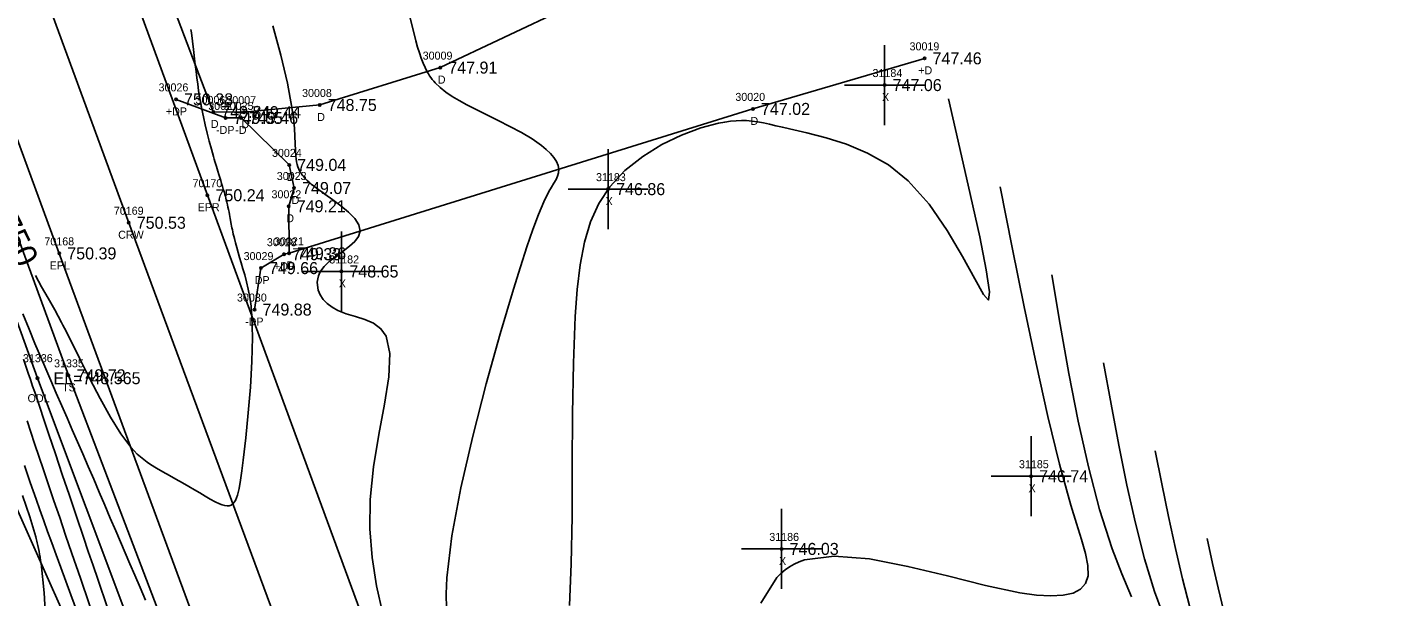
# Model space of a CAD drawing. Extents: x 1376587 to 1378239, y 1000335 to 1003031.
# Drawn here: x 1376699.8 to 1376870.4, y 1002859.9 to 1002931 of the extents above; entities that cross this region are included whole.
import ezdxf

# ---------------------------------------------------------------- set-up
doc = ezdxf.new("R2010")
doc.units = 0
for name, color, linetype in [('RD_DTM_BkLn1', 7, 'Continuous'), ('RD_DTM_BkLn2', 7, 'Continuous'), ('RD_DTM_BkLn_txCode', 7, 'Continuous'), ('RD_DTM_Major1', 7, 'Continuous'), ('RD_DTM_Major1_Lbl', 7, 'Continuous'), ('RD_DTM_Minor1', 7, 'Continuous'), ('RD_EX_Driveway', 7, 'Continuous'), ('RD_EX_Driveway_txCode', 7, 'Continuous'), ('RD_EX_H2O', 7, 'Continuous'), ('RD_EX_H2O_txCode', 7, 'Continuous'), ('RD_EX_Misc', 7, 'Continuous'), ('RD_EX_Misc_txCode', 7, 'Continuous'), ('RD_EX_Road', 7, 'Continuous'), ('RD_EX_Road_txCode', 7, 'Continuous'), ('RD_EX_TX_Driveway_ELEV', 7, 'Continuous'), ('RD_EX_TX_H2O_ELEV', 7, 'Continuous'), ('RD_EX_TX_Misc_ELEV', 7, 'Continuous'), ('RD_EX_TX_Road_ELEV', 7, 'Continuous'), ('RD_HC_Survey_ELEV', 7, 'Continuous'), ('RD_HC_Survey_txCode', 7, 'Continuous'), ('RD_SMD_Locator', 7, 'Continuous')]:
    doc.layers.add(name, color=color, linetype=linetype)

msp = doc.modelspace()

# ---------------------------------------------------------------- linework, layer by layer
at = {"layer": 'RD_DTM_BkLn1'}
msp.add_lwpolyline([(1376777.12, 1002732.3), (1376776.77, 1002733.82), (1376754.91, 1002791.11), (1376734.25, 1002847.87), (1376712.48, 1002906.61), (1376690.98, 1002965.02), (1376668.66, 1003026.02)], dxfattribs=at)
at = {"layer": 'RD_DTM_BkLn2'}
for points in [[(1376885.61, 1002428.98), (1376889.78, 1002434.68), (1376874.69, 1002468.75), (1376852.19, 1002514.33), (1376831.8, 1002561.56), (1376809.96, 1002613.35), (1376792.97, 1002652.8), (1376775.33, 1002700.18), (1376756.39, 1002747.21), (1376739.8, 1002794.07), (1376723.1, 1002839.91), (1376704.95, 1002887.54), (1376687.77, 1002934.36), (1376670.41, 1002980.85)], [(1376885.61, 1002428.97), (1376881.3, 1002430.18), (1376863.13, 1002464.59), (1376838.71, 1002510.16), (1376821.82, 1002559.18), (1376802.89, 1002607.61), (1376786.81, 1002643.28), (1376765.51, 1002696.1), (1376748.39, 1002745.62), (1376732.07, 1002790.52), (1376713.54, 1002837.08), (1376692.71, 1002883.81), (1376675.42, 1002930.22), (1376657.29, 1002975.68)]]:
    msp.add_lwpolyline(points, dxfattribs=at)
at = {"layer": 'RD_DTM_Major1'}
for points in [[(1376720.26, 1002930.77), (1376720.32, 1002930.36), (1376720.45, 1002929.3), (1376720.58, 1002928.27), (1376720.8, 1002926.36), (1376720.9, 1002925.52), (1376721, 1002924.71), (1376721.1, 1002923.92), (1376721.21, 1002923.14), (1376721.33, 1002922.36), (1376721.47, 1002921.57), (1376721.49, 1002921.45), (1376721.52, 1002921.32), (1376721.54, 1002921.2), (1376721.56, 1002921.07), (1376721.61, 1002920.82), (1376721.81, 1002919.85), (1376722.04, 1002918.84), (1376722.29, 1002917.82), (1376722.55, 1002916.8), (1376722.81, 1002915.82), (1376723.06, 1002914.9), (1376723.16, 1002914.57), (1376723.25, 1002914.25), (1376723.44, 1002913.64), (1376723.52, 1002913.35), (1376723.61, 1002913.07), (1376723.74, 1002912.65), (1376723.98, 1002911.88), (1376724.09, 1002911.51), (1376724.2, 1002911.16), (1376724.3, 1002910.82), (1376724.44, 1002910.37), (1376724.5, 1002910.14), (1376724.56, 1002909.92), (1376724.61, 1002909.7), (1376724.67, 1002909.48), (1376724.74, 1002909.17), (1376724.82, 1002908.86), (1376724.88, 1002908.55), (1376724.95, 1002908.25), (1376725.01, 1002907.94), (1376725.07, 1002907.63), (1376725.11, 1002907.39), (1376725.16, 1002907.16), (1376725.29, 1002906.45), (1376725.34, 1002906.2), (1376725.38, 1002905.96), (1376725.44, 1002905.71), (1376725.49, 1002905.46), (1376725.55, 1002905.2), (1376725.61, 1002904.94), (1376725.68, 1002904.66), (1376725.82, 1002904.11), (1376725.98, 1002903.52), (1376726.15, 1002902.91), (1376726.34, 1002902.26), (1376726.54, 1002901.58), (1376726.75, 1002900.87), (1376726.97, 1002900.08), (1376727.2, 1002899.23), (1376727.41, 1002898.32), (1376727.6, 1002897.31), (1376727.76, 1002896.19), (1376727.87, 1002894.94), (1376727.95, 1002892.27), (1376727.87, 1002889.26), (1376727.68, 1002886.06), (1376727.41, 1002882.83), (1376727.1, 1002879.74), (1376726.79, 1002876.92), (1376726.63, 1002875.6), (1376726.46, 1002874.42), (1376726.28, 1002873.4), (1376726.07, 1002872.55), (1376725.81, 1002871.91), (1376725.5, 1002871.47), (1376725.28, 1002871.32), (1376725.04, 1002871.24), (1376724.77, 1002871.22), (1376724.48, 1002871.26), (1376724.17, 1002871.35), (1376723.84, 1002871.48), (1376723.27, 1002871.74), (1376722.67, 1002872.06), (1376722.04, 1002872.43), (1376721.37, 1002872.83), (1376720.69, 1002873.24), (1376719.99, 1002873.66), (1376719.18, 1002874.12), (1376718.37, 1002874.57), (1376717.56, 1002875.01), (1376716.76, 1002875.47), (1376715.97, 1002875.93), (1376715.21, 1002876.41), (1376714.79, 1002876.7), (1376714.37, 1002877), (1376713.96, 1002877.33), (1376713.55, 1002877.69), (1376713.14, 1002878.1), (1376712.73, 1002878.55), (1376711.48, 1002880.23), (1376710.2, 1002882.29), (1376708.91, 1002884.63), (1376707.63, 1002887.11), (1376706.39, 1002889.6), (1376705.2, 1002891.97), (1376705.01, 1002892.35), (1376704.82, 1002892.72), (1376704.45, 1002893.45), (1376704.26, 1002893.8), (1376704.08, 1002894.15), (1376703.23, 1002895.71), (1376702.41, 1002897.2), (1376701.6, 1002898.62), (1376700.83, 1002900)], [(1376827.83, 1002900.11), (1376828.88, 1002893.89), (1376829.97, 1002887.75), (1376831.13, 1002881.79), (1376832.39, 1002876.09), (1376833.79, 1002870.75), (1376835.36, 1002865.84), (1376836.56, 1002862.72), (1376837.77, 1002859.86)], [(1376699.77, 1002881.83), (1376700.23, 1002880.44), (1376700.71, 1002879.02), (1376701.82, 1002875.74), (1376702.47, 1002873.84), (1376703.14, 1002871.84), (1376703.85, 1002869.76), (1376704.59, 1002867.57), (1376705.38, 1002865.28), (1376706.44, 1002862.18), (1376707.55, 1002858.98), (1376708.67, 1002855.76), (1376709.77, 1002852.58), (1376710.82, 1002849.54), (1376711.8, 1002846.71), (1376712.38, 1002845.01), (1376712.93, 1002843.41), (1376713.44, 1002841.92), (1376713.93, 1002840.5), (1376714.39, 1002839.15), (1376714.53, 1002838.74)]]:
    msp.add_lwpolyline(points, dxfattribs=at)
at = {"layer": 'RD_DTM_Minor1'}
for points in [[(1376730.49, 1002931.23), (1376731.47, 1002927.54), (1376732.3, 1002924.06), (1376732.88, 1002921), (1376733.06, 1002919.64), (1376733.18, 1002918.45), (1376733.24, 1002917.4), (1376733.31, 1002915.66), (1376733.36, 1002914.95), (1376733.4, 1002914.58), (1376733.46, 1002914.24), (1376733.53, 1002913.91), (1376733.62, 1002913.6), (1376733.74, 1002913.31), (1376733.88, 1002913.03), (1376734.01, 1002912.8), (1376734.17, 1002912.57), (1376734.35, 1002912.35), (1376734.54, 1002912.12), (1376734.77, 1002911.9), (1376735.01, 1002911.67), (1376735.28, 1002911.44), (1376735.58, 1002911.21), (1376735.89, 1002910.96), (1376736.23, 1002910.71), (1376736.59, 1002910.46), (1376736.97, 1002910.19), (1376737.97, 1002909.48), (1376738.99, 1002908.72), (1376739.94, 1002907.93), (1376740.72, 1002907.12), (1376741.23, 1002906.33), (1376741.4, 1002905.56), (1376741.2, 1002904.9), (1376740.72, 1002904.27), (1376740.05, 1002903.67), (1376739.27, 1002903.07), (1376738.45, 1002902.49), (1376737.68, 1002901.9), (1376737.54, 1002901.77), (1376737.4, 1002901.65), (1376737.26, 1002901.52), (1376737.13, 1002901.4), (1376737.01, 1002901.27), (1376736.9, 1002901.14), (1376736.6, 1002900.76), (1376736.37, 1002900.38), (1376736.2, 1002899.99), (1376736.09, 1002899.59), (1376736.04, 1002899.19), (1376736.05, 1002898.79), (1376736.17, 1002898.19), (1376736.42, 1002897.59), (1376736.79, 1002897.03), (1376737.28, 1002896.51), (1376737.89, 1002896.05), (1376738.59, 1002895.65), (1376739.66, 1002895.24), (1376740.82, 1002894.89), (1376741.98, 1002894.52), (1376743.06, 1002894.04), (1376743.99, 1002893.37), (1376744.66, 1002892.42), (1376745.12, 1002890.26), (1376744.98, 1002887.37), (1376744.45, 1002883.94), (1376743.74, 1002880.13), (1376743.07, 1002876.1), (1376742.64, 1002872.02), (1376742.61, 1002868.36), (1376742.9, 1002864.77), (1376743.46, 1002861.23), (1376744.24, 1002857.71)], [(1376747.62, 1002932.39), (1376748.35, 1002929.36), (1376748.58, 1002928.56), (1376748.8, 1002927.83), (1376749.03, 1002927.17), (1376749.26, 1002926.56), (1376749.51, 1002926), (1376749.77, 1002925.49), (1376749.92, 1002925.23), (1376750.07, 1002924.99), (1376750.24, 1002924.75), (1376750.41, 1002924.53), (1376750.59, 1002924.31), (1376750.78, 1002924.1), (1376751.4, 1002923.5), (1376752.1, 1002922.94), (1376752.89, 1002922.4), (1376753.76, 1002921.87), (1376754.71, 1002921.36), (1376755.73, 1002920.83), (1376757.15, 1002920.13), (1376758.63, 1002919.41), (1376760.11, 1002918.66), (1376761.55, 1002917.88), (1376762.88, 1002917.08), (1376764.05, 1002916.27), (1376764.66, 1002915.76), (1376765.18, 1002915.25), (1376765.6, 1002914.75), (1376765.92, 1002914.25), (1376766.13, 1002913.76), (1376766.22, 1002913.29), (1376766.19, 1002912.86), (1376766.07, 1002912.45), (1376765.87, 1002912.02), (1376765.61, 1002911.56), (1376765.31, 1002911.06), (1376764.99, 1002910.5), (1376764.35, 1002909.21), (1376763.68, 1002907.63), (1376762.98, 1002905.75), (1376762.23, 1002903.58), (1376761.43, 1002901.11), (1376760.57, 1002898.32), (1376758.9, 1002892.71), (1376757.15, 1002886.46), (1376755.47, 1002879.93), (1376753.99, 1002873.48), (1376752.87, 1002867.46), (1376752.24, 1002862.22), (1376752.15, 1002860.22), (1376752.17, 1002858.41)], [(1376814.9, 1002922.09), (1376816.35, 1002915.89), (1376817.68, 1002910.03), (1376818.81, 1002904.86), (1376819.63, 1002900.72), (1376820.02, 1002897.97), (1376819.9, 1002896.94), (1376819.27, 1002897.65), (1376818.19, 1002899.61), (1376816.67, 1002902.41), (1376814.75, 1002905.66), (1376812.48, 1002908.94), (1376809.88, 1002911.85), (1376807.41, 1002913.83), (1376804.81, 1002915.32), (1376802.18, 1002916.43), (1376799.62, 1002917.23), (1376797.21, 1002917.83), (1376795.05, 1002918.33), (1376794.16, 1002918.54), (1376793.33, 1002918.74), (1376792.54, 1002918.93), (1376791.79, 1002919.09), (1376791.05, 1002919.23), (1376790.32, 1002919.32), (1376789.69, 1002919.37), (1376789.04, 1002919.39), (1376788.37, 1002919.36), (1376787.68, 1002919.3), (1376786.95, 1002919.2), (1376786.19, 1002919.06), (1376783.98, 1002918.46), (1376781.57, 1002917.57), (1376779.1, 1002916.37), (1376776.7, 1002914.89), (1376774.48, 1002913.14), (1376772.59, 1002911.11), (1376771.22, 1002909.03), (1376770.18, 1002906.73), (1376769.41, 1002904.17), (1376768.87, 1002901.36), (1376768.5, 1002898.28), (1376768.26, 1002894.91), (1376768.04, 1002889.04), (1376767.94, 1002882.72), (1376767.91, 1002876.24), (1376767.88, 1002869.89), (1376767.77, 1002863.96), (1376767.54, 1002858.75)], [(1376821.37, 1002911.1), (1376822.87, 1002903.53), (1376824.37, 1002896.11), (1376825.85, 1002889.02), (1376827.32, 1002882.41), (1376828.78, 1002876.45), (1376830.2, 1002871.29), (1376830.9, 1002869.03), (1376831.53, 1002867.01), (1376832.03, 1002865.25), (1376832.32, 1002863.75), (1376832.35, 1002862.49), (1376832.05, 1002861.5), (1376831.42, 1002860.8), (1376830.48, 1002860.32), (1376829.23, 1002860.04), (1376827.69, 1002859.96), (1376825.89, 1002860.07), (1376823.83, 1002860.36), (1376819.54, 1002861.27), (1376814.79, 1002862.46), (1376809.85, 1002863.66), (1376805.04, 1002864.58), (1376800.63, 1002864.95), (1376796.93, 1002864.47), (1376796.26, 1002864.24), (1376795.63, 1002863.95), (1376795.04, 1002863.61), (1376794.49, 1002863.21), (1376793.97, 1002862.76), (1376793.48, 1002862.25), (1376791.47, 1002859.06)], [(1376714.56, 1002859.43), (1376713.89, 1002861.03), (1376713.24, 1002862.54), (1376712.62, 1002863.98), (1376712.03, 1002865.37), (1376711.44, 1002866.73), (1376710.86, 1002868.08), (1376710.17, 1002869.7), (1376709.48, 1002871.32), (1376708.79, 1002872.94), (1376708.1, 1002874.55), (1376707.41, 1002876.15), (1376706.73, 1002877.74), (1376706.08, 1002879.23), (1376705.43, 1002880.72), (1376704.77, 1002882.22), (1376704.1, 1002883.74), (1376703.43, 1002885.29), (1376702.73, 1002886.89), (1376702.11, 1002888.36), (1376701.45, 1002889.9), (1376700.76, 1002891.53), (1376700.03, 1002893.3), (1376699.24, 1002895.22)], [(1376699.34, 1002889.57), (1376699.93, 1002887.8), (1376700.21, 1002887), (1376700.47, 1002886.2), (1376700.73, 1002885.44), (1376700.98, 1002884.68), (1376701.49, 1002883.17), (1376701.75, 1002882.39), (1376702.5, 1002880.15), (1376703.32, 1002877.71), (1376704.17, 1002875.15), (1376705.06, 1002872.52), (1376705.94, 1002869.89), (1376706.82, 1002867.3), (1376707.43, 1002865.52), (1376708.02, 1002863.78), (1376708.62, 1002862.04), (1376709.83, 1002858.48)], [(1376834.29, 1002889.12), (1376835.23, 1002883.92), (1376836.2, 1002878.8), (1376837.2, 1002873.82), (1376838.27, 1002869.07), (1376839.42, 1002864.61), (1376840.67, 1002860.52), (1376841.61, 1002857.92)], [(1376840.75, 1002878.12), (1376841.58, 1002873.97), (1376842.41, 1002869.88), (1376843.27, 1002865.9), (1376844.15, 1002862.11), (1376845.07, 1002858.55)], [(1376699.44, 1002876.28), (1376700.18, 1002874.14), (1376700.91, 1002872.05), (1376701.39, 1002870.71), (1376701.86, 1002869.37), (1376702.35, 1002868.01), (1376702.86, 1002866.6), (1376703.41, 1002865.11), (1376703.99, 1002863.53), (1376705.26, 1002860.11), (1376706.64, 1002856.39)], [(1376699.22, 1002872.52), (1376700.13, 1002869.84), (1376700.86, 1002867.34), (1376700.91, 1002867.16), (1376700.95, 1002866.97), (1376701, 1002866.79), (1376701.04, 1002866.61), (1376701.08, 1002866.43), (1376701.12, 1002866.25), (1376701.2, 1002865.89), (1376701.28, 1002865.53), (1376701.34, 1002865.17), (1376701.41, 1002864.8), (1376701.47, 1002864.41), (1376701.53, 1002864.01), (1376701.9, 1002860.35), (1376702.15, 1002855.92)], [(1376847.22, 1002867.13), (1376847.91, 1002864.03), (1376848.61, 1002860.98), (1376849.3, 1002858.01)]]:
    msp.add_lwpolyline(points, dxfattribs=at)
at = {"layer": 'RD_EX_Driveway'}
for points in [[(1376706.51, 1002954.76), (1376715.39, 1002940.55), (1376723.05, 1002920.46), (1376726.88, 1002920.43), (1376736.34, 1002921.33), (1376751.41, 1002926), (1376775.28, 1002937.3), (1376791.56, 1002941.72), (1376806.99, 1002947.41)], [(1376811.92, 1002927.16), (1376790.48, 1002920.84), (1376732.51, 1002902.79), (1376732.47, 1002908.67), (1376733.14, 1002910.95), (1376732.53, 1002913.84), (1376726.51, 1002919.71)], [(1376718.39, 1002922.03), (1376724.58, 1002919.71), (1376726.51, 1002919.71)], [(1376732.51, 1002902.79), (1376731.89, 1002902.68), (1376729, 1002900.94), (1376728.2, 1002895.76)]]:
    msp.add_lwpolyline(points, dxfattribs=at)
at = {"layer": 'RD_EX_H2O'}
msp.add_lwpolyline([(1376884.04, 1002432.1), (1376867.96, 1002466.27), (1376845.47, 1002511.58), (1376827.22, 1002560.38), (1376806.48, 1002611.18), (1376788.41, 1002651.65), (1376772.82, 1002694.38), (1376753.28, 1002747.21), (1376736.65, 1002792.89), (1376719.2, 1002838.91), (1376701.08, 1002887.18), (1376684.58, 1002932.85), (1376667.2, 1002979.87)], dxfattribs=at)
at = {"layer": 'RD_EX_Misc'}
for p, q in [((1376806.93, 1002918.82), (1376806.93, 1002928.82)), ((1376801.93, 1002923.82), (1376811.93, 1002923.82)), ((1376772.38, 1002905.81), (1376772.38, 1002915.81)), ((1376767.38, 1002910.81), (1376777.38, 1002910.81)), ((1376739.05, 1002895.52), (1376739.05, 1002905.52)), ((1376734.05, 1002900.52), (1376744.05, 1002900.52)), ((1376825.23, 1002869.93), (1376825.23, 1002879.93)), ((1376820.23, 1002874.93), (1376830.23, 1002874.93)), ((1376794.06, 1002860.84), (1376794.06, 1002870.84)), ((1376789.06, 1002865.84), (1376799.06, 1002865.84))]:
    msp.add_line(p, q, dxfattribs=at)
at = {"layer": 'RD_EX_Road'}
for points in [[(1376786.56, 1002736.46), (1376786.1, 1002737.56), (1376764.69, 1002795), (1376744.07, 1002850.85), (1376722.32, 1002910.05), (1376701.33, 1002967.35), (1376678.41, 1003028.92)], [(1376768.46, 1002728.84), (1376767.88, 1002730.05), (1376746.2, 1002787.1), (1376725.11, 1002844.98), (1376703.8, 1002902.78), (1376682.09, 1002961.91), (1376659.76, 1003022.67)]]:
    msp.add_lwpolyline(points, dxfattribs=at)
at = {"layer": 'RD_SMD_Locator'}
for centre in [(1376751.41, 1002926), (1376811.92, 1002927.16), (1376806.93, 1002923.82), (1376718.39, 1002922.03), (1376723.05, 1002920.46), (1376726.88, 1002920.43), (1376736.34, 1002921.33), (1376790.48, 1002920.84), (1376724.58, 1002919.71), (1376726.51, 1002919.71), (1376732.53, 1002913.84), (1376733.14, 1002910.95), (1376772.38, 1002910.81), (1376722.32, 1002910.05), (1376732.47, 1002908.67), (1376712.48, 1002906.61), (1376703.8, 1002902.78), (1376731.89, 1002902.68), (1376732.51, 1002902.79), (1376729, 1002900.94), (1376739.05, 1002900.52), (1376728.2, 1002895.76), (1376701.08, 1002887.18), (1376704.95, 1002887.54), (1376825.23, 1002874.93), (1376794.06, 1002865.84)]:
    msp.add_circle(centre, 0.15, dxfattribs=at)

# ---------------------------------------------------------------- texts
at = {"layer": 'RD_DTM_BkLn_txCode'}
for s, p in [('31335', (1376703.15, 1002888.54)), ('TS', (1376704.15, 1002885.54))]:
    msp.add_text(s, height=1, dxfattribs=at).set_placement(p)
at = {"layer": 'RD_DTM_Major1_Lbl'}
msp.add_text('750', height=3, rotation=295.8236, dxfattribs=at).set_placement((1376695.71, 1002906.85))
at = {"layer": 'RD_EX_Driveway_txCode'}
for s, p in [('30019', (1376810.05, 1002928.16)), ('30009', (1376749.21, 1002927)), ('+D', (1376811.13, 1002925.16)), ('30026', (1376716.21, 1002923.03)), ('D', (1376751.1, 1002924)), ('30006', (1376720.83, 1002921.46)), ('30007', (1376724.68, 1002921.43)), ('30008', (1376734.14, 1002922.33)), ('30020', (1376788.28, 1002921.84)), ('+DP', (1376717.12, 1002920.03)), ('30027', (1376722.42, 1002920.71)), ('30025', (1376724.35, 1002920.71)), ('D', (1376722.74, 1002918.46)), ('D', (1376726.57, 1002918.43)), ('D', (1376736.03, 1002919.33)), ('D', (1376790.17, 1002918.84)), ('-DP', (1376723.39, 1002917.71)), ('-D', (1376725.79, 1002917.71)), ('30024', (1376730.38, 1002914.84)), ('30023', (1376730.98, 1002911.95)), ('D', (1376732.23, 1002911.84)), ('30022', (1376730.32, 1002909.67)), ('D', (1376732.83, 1002908.95)), ('D', (1376732.17, 1002906.67)), ('30028', (1376729.74, 1002903.68)), ('30021', (1376730.64, 1002903.79)), ('30029', (1376726.84, 1002901.94)), ('D', (1376732.2, 1002900.79)), ('+DP', (1376730.63, 1002900.68)), ('DP', (1376728.22, 1002898.94)), ('30030', (1376726.01, 1002896.76)), ('-DP', (1376727.02, 1002893.76))]:
    msp.add_text(s, height=1, dxfattribs=at).set_placement(p)
at = {"layer": 'RD_EX_H2O_txCode'}
for s, p in [('31336', (1376699.26, 1002889.18)), ('ODL', (1376699.84, 1002884.18))]:
    msp.add_text(s, height=1, dxfattribs=at).set_placement(p)
at = {"layer": 'RD_EX_Misc_txCode'}
for s, p in [('31184', (1376805.42, 1002924.82)), ('X', (1376806.61, 1002921.82)), ('31183', (1376770.87, 1002911.81)), ('X', (1376772.07, 1002908.81)), ('31182', (1376737.54, 1002901.52)), ('X', (1376738.73, 1002898.52)), ('31185', (1376823.72, 1002875.93)), ('X', (1376824.92, 1002872.93)), ('31186', (1376792.52, 1002866.84)), ('X', (1376793.74, 1002863.84))]:
    msp.add_text(s, height=1, dxfattribs=at).set_placement(p)
at = {"layer": 'RD_EX_Road_txCode'}
for s, p in [('70170', (1376720.45, 1002911.05)), ('EPR', (1376721.09, 1002908.05)), ('70168', (1376701.94, 1002903.78)), ('EPL', (1376702.6, 1002900.78))]:
    msp.add_text(s, height=1, dxfattribs=at).set_placement(p)
at = {"layer": 'RD_EX_TX_Driveway_ELEV'}
for s, p in [('747.46', (1376812.92, 1002926.41)), ('747.91', (1376752.41, 1002925.25)), ('750.38', (1376719.39, 1002921.28)), ('749.84', (1376724.05, 1002919.71)), ('749.44', (1376727.88, 1002919.68)), ('748.75', (1376737.34, 1002920.58)), ('747.02', (1376791.48, 1002920.09)), ('749.65', (1376725.58, 1002918.96)), ('749.46', (1376727.51, 1002918.96)), ('749.04', (1376733.53, 1002913.09)), ('749.07', (1376734.14, 1002910.2)), ('749.21', (1376733.47, 1002907.92)), ('749.36', (1376733.51, 1002902.04)), ('749.33', (1376732.89, 1002901.93)), ('749.66', (1376730, 1002900.19)), ('749.88', (1376729.2, 1002895.01))]:
    msp.add_text(s, height=1.5, dxfattribs=at).set_placement(p)
at = {"layer": 'RD_EX_TX_H2O_ELEV'}
msp.add_text('EL=748.565', height=1.5, dxfattribs=at).set_placement((1376703.08, 1002886.43))
at = {"layer": 'RD_EX_TX_Misc_ELEV'}
for s, p in [('747.06', (1376807.93, 1002923.07)), ('746.86', (1376773.38, 1002910.06)), ('748.65', (1376740.05, 1002899.77)), ('749.72', (1376705.95, 1002886.79)), ('746.74', (1376826.23, 1002874.18)), ('746.03', (1376795.06, 1002865.09))]:
    msp.add_text(s, height=1.5, dxfattribs=at).set_placement(p)
at = {"layer": 'RD_EX_TX_Road_ELEV'}
for s, p in [('750.24', (1376723.32, 1002909.3)), ('750.39', (1376704.8, 1002902.03))]:
    msp.add_text(s, height=1.5, dxfattribs=at).set_placement(p)
at = {"layer": 'RD_HC_Survey_ELEV'}
msp.add_text('750.53', height=1.5, dxfattribs=at).set_placement((1376713.48, 1002905.86))
at = {"layer": 'RD_HC_Survey_txCode'}
for s, p in [('70169', (1376710.62, 1002907.61)), ('CRW', (1376711.16, 1002904.61))]:
    msp.add_text(s, height=1, dxfattribs=at).set_placement(p)

doc.saveas('drawing.dxf')
